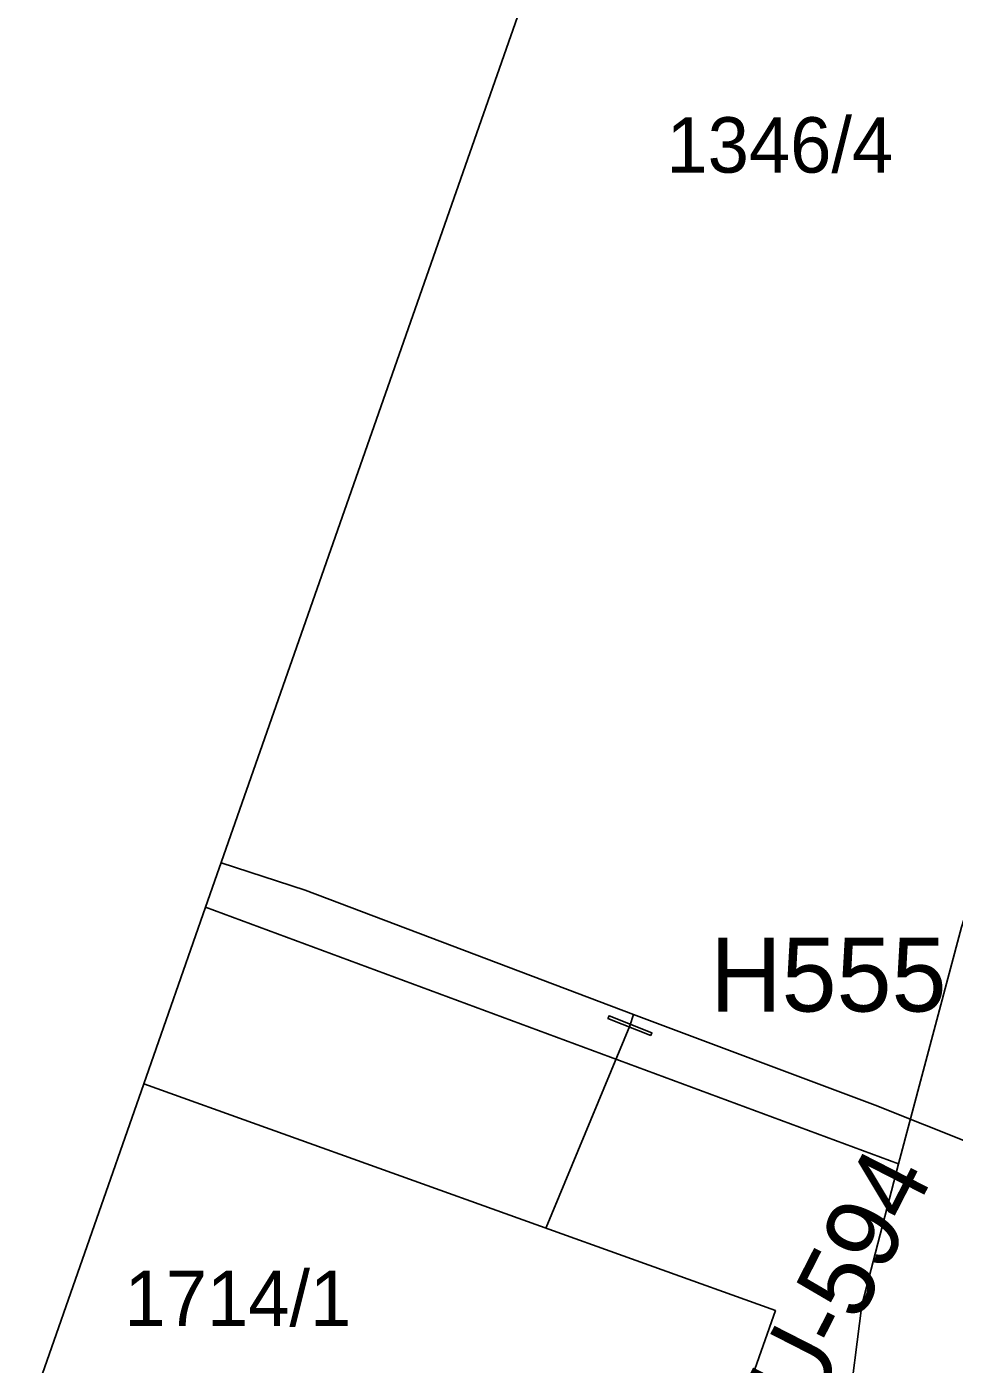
# Model space of a CAD drawing. Extents: x -562248 to -562040, y -1079385 to -1079027.
# Drawn here: x -562154.88 to -562129.79, y -1079101.77 to -1079065.59 of the extents above; entities that cross this region are included whole.
import ezdxf

# ---------------------------------------------------------------- set-up
doc = ezdxf.new("R2010")
doc.units = 0
for name, color, linetype in [('Armatura - popis', 7, 'Continuous'), ('Armatura vodovodní', 7, 'Continuous'), ('Označení hydrantu', 7, 'Continuous'), ('Parcela-polygon', 7, 'Continuous'), ('Parcela-text', 7, 'Continuous'), ('Vodovodní přípojka', 7, 'Continuous'), ('Vodovodní řad', 7, 'Continuous')]:
    doc.layers.add(name, color=color, linetype=linetype)

msp = doc.modelspace()

# ---------------------------------------------------------------- linework, layer by layer
at = {"layer": 'Armatura vodovodní'}
msp.add_lwpolyline([(-562138, -1079092.88), (-562137.971, -1079092.807), (-562139.133, -1079092.347), (-562139.162, -1079092.419)], close=True, dxfattribs=at)
at = {"layer": 'Parcela-polygon'}
for p, q in [((-562134.941, -1079046.267), (-562150.044, -1079089.409)), ((-562150.044, -1079089.409), (-562151.717, -1079094.19)), ((-562151.717, -1079094.19), (-562154.883, -1079103.233))]:
    msp.add_line(p, q, dxfattribs=at)
for points in [[(-562150.044, -1079089.409), (-562131.3, -1079096.35), (-562129.6, -1079089.95), (-562127.9, -1079084.66), (-562116.47, -1079053.33), (-562116.62, -1079052.94), (-562134.941, -1079046.267)], [(-562122.69, -1079105.05), (-562122.05, -1079101.16), (-562121.03, -1079096.76), (-562119.65, -1079091.82), (-562106.84, -1079056.62), (-562116.62, -1079052.94), (-562116.47, -1079053.33), (-562127.9, -1079084.66), (-562129.6, -1079089.95), (-562131.3, -1079096.35), (-562132.29, -1079100.17), (-562132.68, -1079103.22)], [(-562151.717, -1079094.19), (-562134.63, -1079100.32), (-562137.81, -1079109.35), (-562138.38, -1079111.23), (-562133.03, -1079111.66), (-562133.02, -1079110.27), (-562132.95, -1079106.27), (-562132.68, -1079103.22), (-562132.29, -1079100.17), (-562131.3, -1079096.35), (-562150.044, -1079089.409)], [(-562154.883, -1079103.233), (-562137.81, -1079109.35), (-562134.63, -1079100.32), (-562151.717, -1079094.19)]]:
    msp.add_lwpolyline(points, dxfattribs=at)
at = {"layer": 'Vodovodní přípojka'}
msp.add_lwpolyline([(-562140.83, -1079098.07), (-562138.567, -1079092.614), (-562138.471, -1079092.308)], dxfattribs=at)
at = {"layer": 'Vodovodní řad'}
msp.add_lwpolyline([(-562128.13, -1079096.11), (-562128.608, -1079096.027), (-562129.262, -1079095.825), (-562131.937, -1079094.765), (-562138.471, -1079092.308), (-562147.354, -1079088.946), (-562149.623, -1079088.208)], dxfattribs=at)

# ---------------------------------------------------------------- texts
at = {"layer": 'Armatura - popis'}
msp.add_text('SU-594', height=2, rotation=62.9511, dxfattribs=at).set_placement((-562134.473, -1079104.765))
at = {"layer": 'Označení hydrantu'}
msp.add_text('H555', height=2, dxfattribs=at).set_placement((-562136.397, -1079092.231))
at = {"layer": 'Parcela-text'}
for s, p in [('1346/4', (-562137.58, -1079069.54)), ('1714/1', (-562152.24, -1079100.74))]:
    msp.add_text(s, height=1.5, dxfattribs=at).set_placement(p)

doc.saveas('drawing.dxf')
